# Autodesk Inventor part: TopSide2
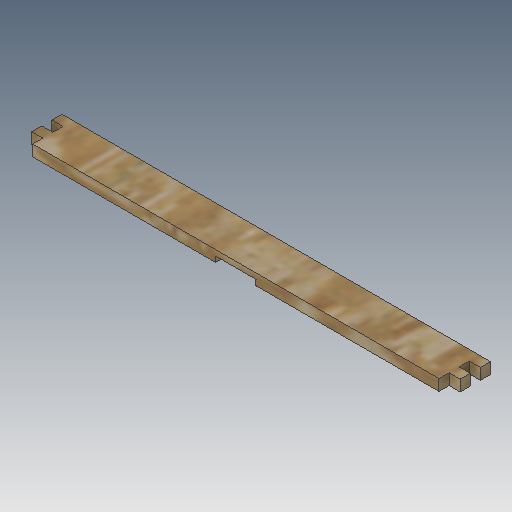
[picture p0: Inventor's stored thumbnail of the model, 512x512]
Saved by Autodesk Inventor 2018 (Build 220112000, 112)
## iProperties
Created: 2018-05
Part Number: TopSide2
Material: Generic
Document SubType Name: Modeling
Designer: arivu
Density: 1 g/cm^3
Appearance: Default
Author: arivu
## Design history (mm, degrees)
derived "WaterTank.ipt"
feature "Solid14::WaterTank.ipt" dims "d0" = 10
tag "TaggingFeature1"
body "Solid1"
